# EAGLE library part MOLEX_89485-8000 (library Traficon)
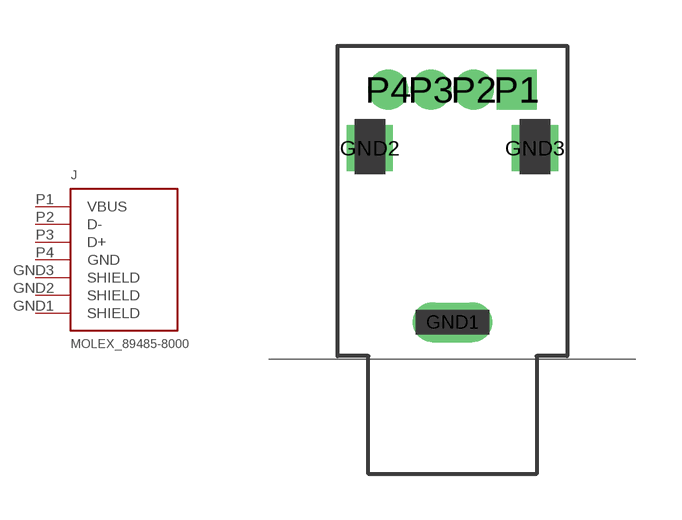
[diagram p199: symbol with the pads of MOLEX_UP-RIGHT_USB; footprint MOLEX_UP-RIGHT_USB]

Designator prefix J

## MOLEX_89485-8000  [MOLEX_UP-RIGHT_USB]
GND1  SHIELD
GND2  SHIELD
GND3  SHIELD
P1  VBUS
P2  D-
P3  D+
P4  GND

## Footprint MOLEX_UP-RIGHT_USB (pad centres in mm)
drill 0.8 long: GND1 0,0
drill 1 square: GND2 -2.7,5.7; GND3 2.7,5.7
drill 0.8 square: P1 2.1,7.62
drill 0.8 round: P2 0.7,7.62; P3 -0.7,7.62; P4 -2.1,7.62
